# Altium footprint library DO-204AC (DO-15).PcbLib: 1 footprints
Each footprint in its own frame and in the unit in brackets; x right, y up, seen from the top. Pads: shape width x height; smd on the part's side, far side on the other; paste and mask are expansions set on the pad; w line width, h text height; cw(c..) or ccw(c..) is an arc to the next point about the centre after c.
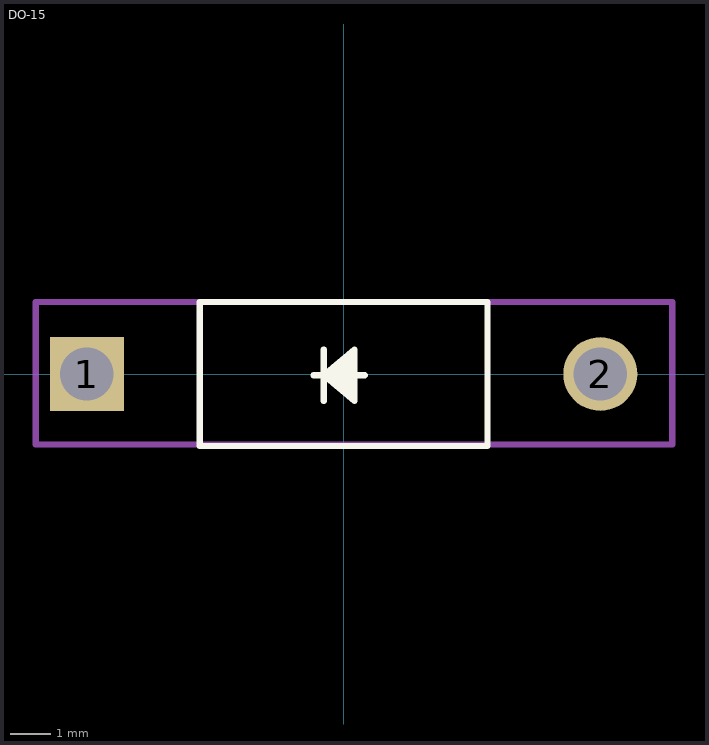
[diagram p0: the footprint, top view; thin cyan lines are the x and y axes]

## DO-15 [mil]
pads (2):
  rect 72x72 hole 52: 1(-250,0)
  round 72 hole 52: 2(250,0)
Top Overlay:
  lines w6: -29.37,-1.29 20.63,-1.29 ; -19.37,-26.29 -19.37,23.71 ; 10.63,-21.29 -19.37,-1.29 ; 10.63,-16.29 -19.37,-1.29 ; 10.63,-11.29 -19.37,-1.29 ; 10.63,-6.29 -19.37,-1.29 ; 10.63,3.71 -19.37,-1.29 ; 10.63,8.71 -19.37,-1.29 ; 10.63,13.71 -19.37,-1.29 ; 10.63,18.71 -19.37,-1.29 ; -19.37,-1.29 10.63,-26.29 10.63,23.71 -19.37,-1.29 ; -140,-70 -140,70 140,70 140,-70 -140,-70
Mechanical 15:
  lines w6: -299.69,-68.76 120.26,-68.76 320,-68.76 320,70 -299.69,70 -299.69,-68.76
3D body "User Library-DO-15-2.STEP": height 195.2, standoff -71.73, extent -266.54,-68.66 267.32,71.5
